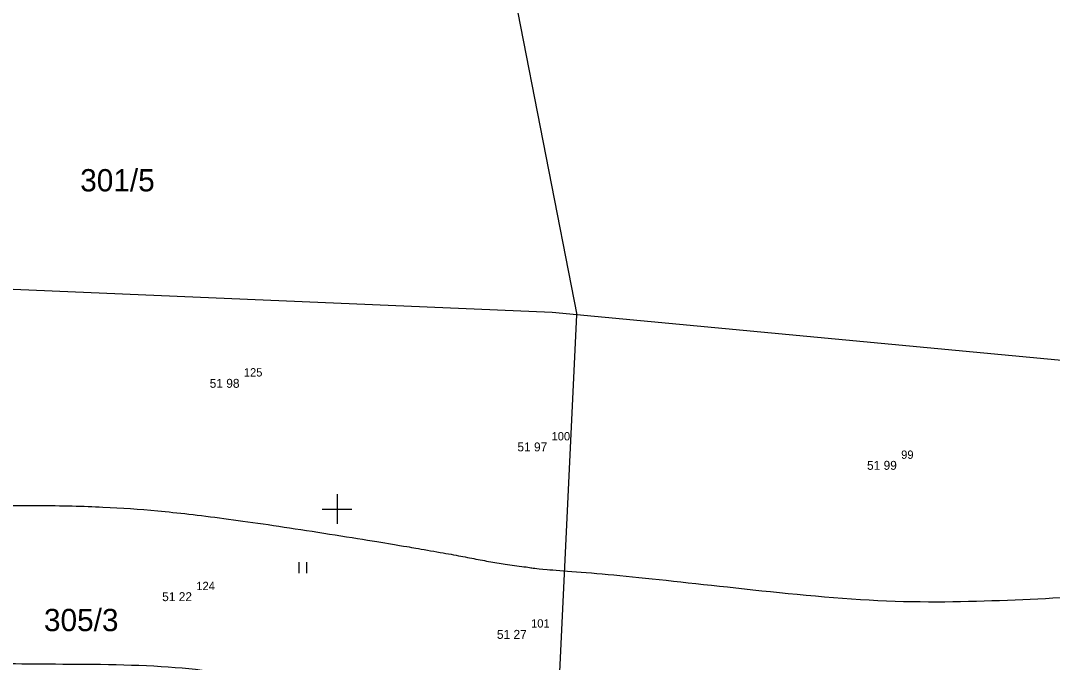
# Model space of a CAD drawing. Extents: x -704057 to -703795, y -1008732 to -1008584.
# Drawn here: x -703910.66 to -703875.92, y -1008655.16 to -1008633.56 of the extents above; entities that cross this region are included whole.
import ezdxf

# ---------------------------------------------------------------- set-up
doc = ezdxf.new("R2010")
doc.units = 0
for name, color, linetype in [('Z_body', 7, 'Continuous'), ('Z_body_cisla', 7, 'Continuous'), ('Z_body_vysky', 7, 'Continuous'), ('Z_hekt_sit', 7, 'Continuous'), ('Z_katastr_cisla_pozemkove', 7, 'Continuous'), ('Z_katastr_hranice', 7, 'Continuous'), ('Z_popis', 7, 'Continuous'), ('Z_vrstevnice_popis', 7, 'Continuous'), ('Z_vrstevnice_vedlejsi', 7, 'Continuous')]:
    doc.layers.add(name, color=color, linetype=linetype)

# ---------------------------------------------------------------- blocks, each defined once
blk = doc.blocks.new('POINT_DISPLAY')
blk.add_line((0, 0), (0, 0))
blk = doc.blocks.new('Z306')
for p, q in [((-0.13, 0.17), (-0.13, -0.2)), ((0.13, 0.17), (0.13, -0.2))]:
    blk.add_line(p, q)

msp = doc.modelspace()

# ---------------------------------------------------------------- linework, layer by layer
at = {"layer": 'Z_hekt_sit'}
for p, q in [((-703900, -1008649.5), (-703900, -1008650.5)), ((-703900.5, -1008650), (-703899.5, -1008650))]:
    msp.add_line(p, q, dxfattribs=at)
at = {"layer": 'Z_katastr_hranice'}
for p, q in [((-703894.73, -1008629.15), (-703891.93, -1008643.46)), ((-703892.76, -1008643.39), (-703914.78, -1008642.45)), ((-703891.93, -1008643.46), (-703892.76, -1008643.39)), ((-703892.72, -1008660.17), (-703891.93, -1008643.46)), ((-703807.93, -1008651.42), (-703891.93, -1008643.46))]:
    msp.add_line(p, q, dxfattribs=at)
at = {"layer": 'Z_vrstevnice_popis'}
msp.add_open_spline([(-703958.782, -1008656.452), (-703958.711, -1008656.345), (-703958.126, -1008655.591), (-703956.246, -1008655.482), (-703959.788, -1008654.246), (-703961.93, -1008651.293), (-703961.78, -1008651.126), (-703959.248, -1008651.187), (-703958.2, -1008651.305), (-703958.136, -1008651.315), (-703958.106, -1008651.318), (-703958.062, -1008651.325), (-703957.976, -1008651.334), (-703949.197, -1008652.35), (-703949.055, -1008652.366), (-703948.978, -1008652.372), (-703948.89, -1008652.368), (-703940.582, -1008653.06), (-703940.108, -1008653.095), (-703933.647, -1008653.758), (-703931.403, -1008653.997), (-703930.745, -1008653.985), (-703930.26, -1008654), (-703929.245, -1008652.825), (-703928.701, -1008652.453), (-703928.643, -1008652.6), (-703928.429, -1008652.279), (-703926.218, -1008652.574), (-703924.884, -1008652.504), (-703924.716, -1008652.484), (-703922.063, -1008653.995), (-703921.911, -1008654.006), (-703921.781, -1008654.024), (-703921.558, -1008654.048), (-703920.173, -1008654.162), (-703919.91, -1008654.188), (-703916.508, -1008654.023), (-703914.694, -1008654.331), (-703914.465, -1008654.432), (-703913.706, -1008654.968), (-703913.145, -1008655.151), (-703910.497, -1008655.228), (-703905.972, -1008655.203), (-703903.752, -1008655.504), (-703902.532, -1008655.695)], degree=3, dxfattribs=at)
at = {"layer": 'Z_vrstevnice_vedlejsi'}
msp.add_open_spline([(-704009.362, -1008633.586), (-704007.915, -1008634.739), (-704007.143, -1008635.358), (-704002.876, -1008638.286), (-704002.679, -1008638.43), (-704002.255, -1008638.718), (-704001.165, -1008638.717), (-703995.889, -1008642.289), (-703994.89, -1008642.862), (-703994.417, -1008642.752), (-703993.832, -1008642.719), (-703993.258, -1008640.696), (-703993.341, -1008639.701), (-703993.272, -1008639.432), (-703993.04, -1008638.835), (-703992.99, -1008638.745), (-703990.403, -1008638.423), (-703989.481, -1008638.539), (-703989.058, -1008638.588), (-703989.018, -1008638.516), (-703988.578, -1008638.54), (-703988.475, -1008638.554), (-703988.362, -1008638.685), (-703988.319, -1008638.754), (-703988.294, -1008638.815), (-703986.637, -1008641.391), (-703986.518, -1008641.581), (-703985.267, -1008643.657), (-703984.422, -1008644.955), (-703982.223, -1008646.72), (-703982.083, -1008646.9), (-703980.47, -1008647.779), (-703979.335, -1008647.914), (-703971.793, -1008648.878), (-703969.312, -1008649.063), (-703968.076, -1008649.117), (-703960.948, -1008649.919), (-703959.282, -1008650.186), (-703958.493, -1008650.28), (-703957.367, -1008650.455), (-703955.116, -1008650.684), (-703950.816, -1008651.182), (-703948.3, -1008651.463), (-703946.953, -1008651.576), (-703945.397, -1008651.505), (-703943.023, -1008651.703), (-703939.161, -1008651.987), (-703938.27, -1008652.079), (-703937.191, -1008652.194), (-703934.147, -1008651.524), (-703931.028, -1008650.815), (-703930.717, -1008650.764), (-703928.94, -1008650.83), (-703928.501, -1008650.751), (-703928.424, -1008650.713), (-703928.413, -1008650.708), (-703928.266, -1008650.724), (-703926.027, -1008648.737), (-703920.5, -1008648.624), (-703915.824, -1008649.925), (-703908.88, -1008649.843), (-703904.651, -1008650.155), (-703897.103, -1008651.333), (-703893.743, -1008651.997), (-703889.99, -1008652.252), (-703881.693, -1008653.228), (-703874.656, -1008652.961), (-703868.448, -1008652.365), (-703859.857, -1008652.906), (-703856.36, -1008653.001), (-703843.765, -1008653.766), (-703842.17, -1008653.801), (-703841.143, -1008653.824), (-703831.904, -1008654.28)], degree=2, dxfattribs=at)

# ---------------------------------------------------------------- block references
at = {"layer": 'Z_body'}
for p in [(-703903.64, -1008645.62), (-703893.28, -1008647.76), (-703881.51, -1008648.38), (-703905.24, -1008652.8), (-703893.97, -1008654.07)]:
    msp.add_blockref('POINT_DISPLAY', p, dxfattribs=at)
at = {"layer": 'Z_popis'}
msp.add_blockref('Z306', (-703901.16, -1008651.96), dxfattribs=at)

# ---------------------------------------------------------------- texts
at = {"layer": 'Z_body_cisla'}
for s, p in [('125', (-703903.14, -1008645.54)), ('100', (-703892.78, -1008647.69)), ('99', (-703881.01, -1008648.31)), ('124', (-703904.74, -1008652.73)), ('101', (-703893.47, -1008653.99))]:
    msp.add_text(s, height=0.28, dxfattribs=at).set_placement(p)
at = {"layer": 'Z_body_vysky'}
for s, p in [('51 98', (-703904.29, -1008645.92)), ('51 97', (-703893.93, -1008648.06)), ('51 99', (-703882.16, -1008648.68)), ('51 22', (-703905.89, -1008653.1)), ('51 27', (-703894.62, -1008654.37))]:
    msp.add_text(s, height=0.3, dxfattribs=at).set_placement(p)
at = {"layer": 'Z_katastr_cisla_pozemkove'}
for s, p in [('301/5', (-703908.65, -1008639.31)), ('305/3', (-703909.87, -1008654.11))]:
    msp.add_text(s, height=0.75, dxfattribs=at).set_placement(p)

doc.saveas('drawing.dxf')
